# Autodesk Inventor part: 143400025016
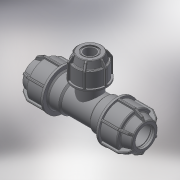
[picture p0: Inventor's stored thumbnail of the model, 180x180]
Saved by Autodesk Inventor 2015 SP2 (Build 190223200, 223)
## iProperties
Created: 2017-08
Part Number: 143400025016
Material: Generic
Description: PLASSON L.14 TEE REDUCER (SILVER) 25-16-25
Document SubType Name: Modeling
Designer: KIM
Density: 1 g/cm^3
Appearance: Default
Author: KIM
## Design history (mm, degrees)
derived "143400.ipt"
feature "Solid1::143400.ipt"
feature "Solid2::143400.ipt"
tag "TaggingFeature1"
body "Solid1"
body "Solid2"
other parameters: "d1" = 25, "d2" = 48, "d4" = 15 deg, "d5" = 31.68, "d6" = 10.4544, "d16" = 25.5, "d17" = 2.4, "d24" = 2.4, "d25" = 45, "d26" = 37.5, "d27" = 2.4, "d28" = 135 deg, "d29" = 1.44, "d31" = 1.25, "d46" = 150 deg, "d49" = 2.5, "d50" = 0, "d58" = 0.75, "d61" = 360 deg, "d63" = 22.5, "d64" = 62, "d80" = 36, "d81" = 2, "d84" = 2.4, "d108" = 0.75, "d111" = 0, "d113" = 11.2, "d114" = 34, "d115" = 17, "d116" = 1.7, "d118" = 25, "d119" = 7.5, "d120" = 30.6, "d121" = 26.52, "d122" = 13 deg, "d123" = 16, "d124" = 0.5, "d125" = 1.5, "d126" = 17.6, "d127" = 13.6, "d128" = 22.4, "d129" = 15 deg, "d130" = 2.5, "d131" = 0, "d132" = 1.6, "d133" = 0.32, "d135" = 360 deg, "d_" = 25, "d_1" = 16, "L_" = 124, "l_" = 48, "l_2" = 17, "E_1" = 34
